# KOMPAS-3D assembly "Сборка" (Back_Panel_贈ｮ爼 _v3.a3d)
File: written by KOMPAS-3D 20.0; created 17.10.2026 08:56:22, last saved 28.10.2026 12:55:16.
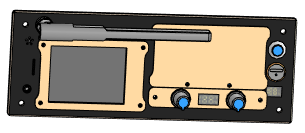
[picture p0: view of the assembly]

Document properties: Полное имя файла: D:\RicWork\Project-EPS32\box_compas\сборки компонентов\Back_Panel_Сборка_v3.a3d

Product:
- Part/product: Сборка
    Масса: 1.58002
  - Component [detail]: Деталь  | Масса: 0.00511556; source file: ..\переключатели и кнопки\indicator typa A with button.m3d
  - Component [detail]: Деталь  | Масса: 0.00714876; source file: ..\переключатели и кнопки\indicator typa B without button.m3d
  - Component [assembly]: Сборка  | Масса: 0.245619; source file: ILI9341_86_50_DevBoard.a3d
  - Component [assembly]: Сборка  | Масса: 0.0237077; source file: ..\переключатели и кнопки\button_momentary self-reset 12 asm.a3d
  - Component [assembly]: Сборка  | Масса: 0.0750813; source file: ..\корпус\крышка на батарейный отсек v3 asm.a3d
  - Component [detail]: Деталь  | Масса: 0.0229921; source file: ..\корпус\крышка на монитор.m3d
  - Component [detail]: Деталь  | Масса: 0.0739347; source file: ..\корпус\крышка на батарейный отсек v2.m3d
  - Component [detail]: Деталь  | qty 4  | Масса: 0.000148431; source file: ..\прочее\Латунные рифленые гайки HUI JI.m3d
  - Component [assembly]: Сборка  | Масса: 0.108754; source file: панель кнопок asm.a3d
  - Component [assembly]: Сборка  | Масса: 0.0501572; source file: panel_ir_sd_jack_asm.a3d
  - Component [assembly]: Сборка  | Масса: 0.425781; source file: ..\ups 18650\my_ups_asm.a3d
  - Component [detail]: Деталь  | Масса: 0.0197779; source file: ..\разъемы\USB-C_Type-C.m3d
  - Component [detail]: Деталь  | Масса: 0.0223332; source file: ..\корпус\п-стойка_2_r.m3d
  - Component [detail]: Деталь  | Масса: 0.0248378; source file: ..\корпус\п-стойка_2_l.m3d
  - Component [assembly]: Сборка  | Масса: 0.120303; source file: ..\wifi\antenna wifi_asm.a3d
  - Component [detail]: Деталь  | Материал: Фанера, береза,ФСФ ВВ/С ГОСТ 3916.1-2018 (density 760 kg/m3); Масса: 0.0216848; source file: ..\корпус\back_panel_v3.m3d
  - Component [assembly]: Сборка  | Масса: 0.261942; source file: ILI9341_81_50_DevBoard.a3d
  - Component [assembly]: Сборка  | Масса: 0.0702532; source file: панель кнопок v2 asm.a3d

Referenced files in D:\RicWork\Project-EPS32\box_compas\корпус\: back_panel_v3.m3d, п-стойка_2_l.m3d, п-стойка_2_r.m3d, крышка на батарейный отсек v2.m3d, крышка на монитор.m3d, крышка на батарейный отсек v3 asm.a3d
Referenced files in D:\RicWork\Project-EPS32\box_compas\wifi\: antenna wifi_asm.a3d
Referenced files in D:\RicWork\Project-EPS32\box_compas\переключатели и кнопки\: button_momentary self-reset 12 asm.a3d, indicator typa B without button.m3d, indicator typa A with button.m3d
Referenced files in D:\RicWork\Project-EPS32\box_compas\сборки компонентов\: panel_ir_sd_jack_asm.a3d, панель кнопок asm.a3d, ILI9341_81_50_DevBoard.a3d, ILI9341_86_50_DevBoard.a3d, панель кнопок v2 asm.a3d
Referenced files in D:\RicWork\Project-EPS32\box_compas\прочее\: Латунные рифленые гайки HUI JI.m3d
Referenced files in D:\RicWork\Project-EPS32\box_compas\разъемы\: USB-C_Type-C.m3d
Referenced files in D:\RicWork\Project-EPS32\box_compas\ups 18650\: my_ups_asm.a3d
Referenced files in D:\myProjects\Progect_esp32\box_compas\прочее\: Латунные рифленые гайки HUI JI.m3d
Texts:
  Деталь (1)
  Деталь (2)
  Деталь (3)
  Деталь (4)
